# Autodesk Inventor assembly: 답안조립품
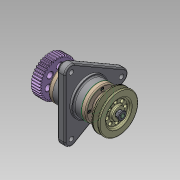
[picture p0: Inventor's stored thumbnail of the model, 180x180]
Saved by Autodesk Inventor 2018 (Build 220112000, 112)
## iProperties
Created: 2023-04
Part Number: 답안조립품
Material: 일반
Document SubType Name: Assembly
Designer: home
Author: home
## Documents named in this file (11)
- C:\Users\home\Desktop\730407V1016\답안조립품.iam
- C:\Users\home\Desktop\730407V1016\본체.ipt
- C:\Users\home\Desktop\730407V1016\축.ipt
- C:\Users\home\Desktop\730407V1016\묻힘키 5x5x16.ipt
- C:\Users\home\Desktop\730407V1016\6각 플랜지 너트 M10.ipt
- C:\Users\home\Desktop\730407V1016\v-벨트풀리.ipt
- C:\Users\home\Desktop\730407V1016\오일 실 20 32 8.ipt
- C:\Users\home\Desktop\730407V1016\베어링 6204.ipt
- C:\Users\home\Desktop\730407V1016\커버.ipt
- C:\Users\home\Desktop\730407V1016\볼트 M4 x 12.ipt
- C:\Users\home\Desktop\730407V1016\스퍼기어.ipt
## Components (3 placed, 2 different names)
1. 6각 플랜지 너트 M10:1
2. v-벨트풀리:1
3. 6각 플랜지 너트 M10:2
